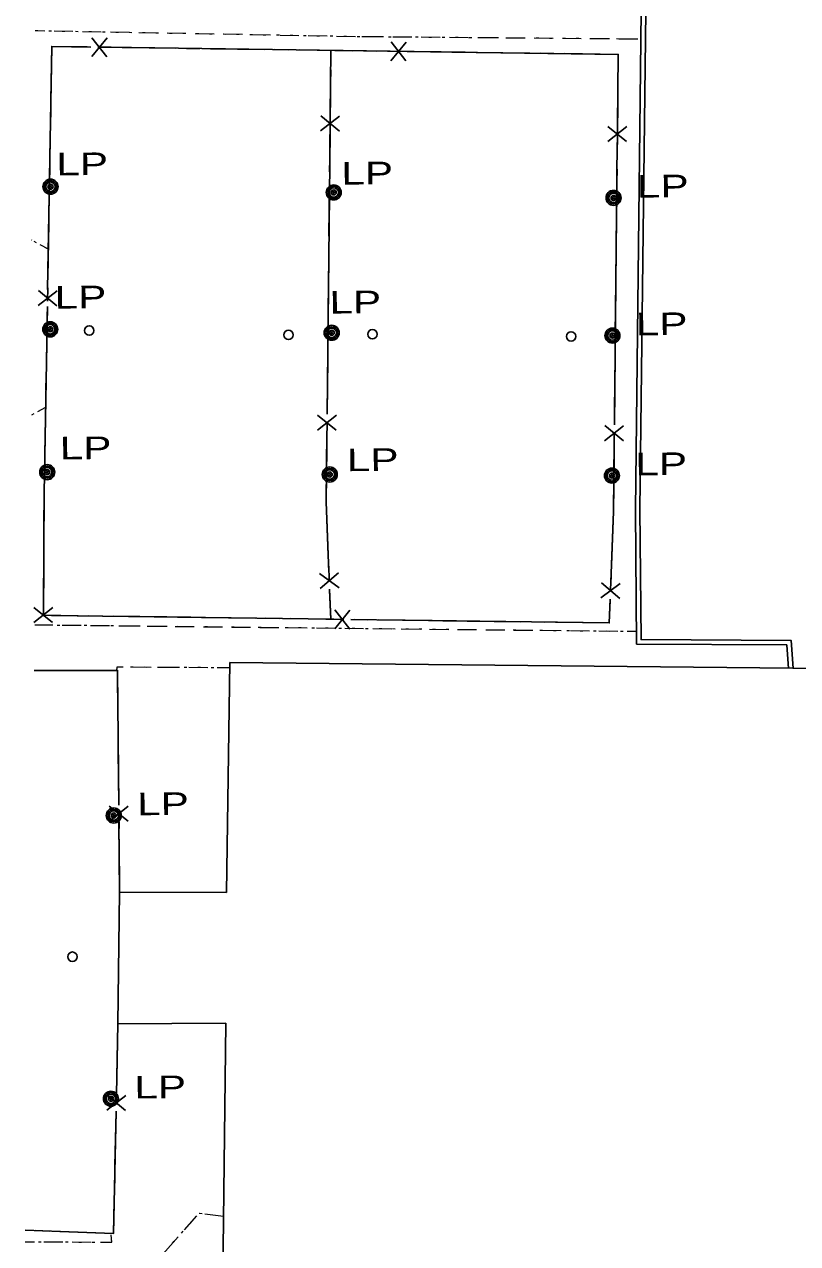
# Model space of a CAD drawing. Extents: x 2362213 to 2366494, y 6968794 to 6978110.
# Drawn here: x 2363840.6 to 2364004.9, y 6973596.3 to 6973855.4 of the extents above; entities that cross this region are included whole.
import ezdxf

# ---------------------------------------------------------------- set-up
doc = ezdxf.new("R2010")
doc.units = 0
doc.header["$LTSCALE"] = 1.9
doc.linetypes.add('DOTTED', pattern=[1.5, 0.3, -1.2])
doc.linetypes.add('LONG_DASH_SHORT_DASH', pattern=[9.9, 6, -1.2, 1.5, -1.2])
for name, color, linetype, lineweight in [('11', 7, 'Continuous', 25), ('13', 7, 'Continuous', 13), ('17', 7, 'Continuous', 25), ('2', 7, 'Continuous', 25), ('20', 7, 'Continuous', 25)]:
    doc.layers.add(name, color=color, linetype=linetype, lineweight=lineweight)

msp = doc.modelspace()

# ---------------------------------------------------------------- linework, layer by layer
at = {"layer": '11'}
msp.add_lwpolyline([(2363882.575, 6973571.486), (2363883.372, 6973643.127), (2363860.452, 6973643.018), (2363860.826, 6973671.023), (2363883.517, 6973670.959), (2363884.282, 6973719.809), (2364017.991, 6973718.463), (2364017.316, 6973661.333), (2364030.594, 6973657.349), (2364031.804, 6973749.765)], dxfattribs=at)
at = {"layer": '13'}
for p, q in [((2363842.911, 6973854.112), (2363844.912, 6973854.071)), ((2363846.912, 6973854.04), (2363850.913, 6973853.968)), ((2363852.914, 6973853.927), (2363856.915, 6973853.855)), ((2363858.915, 6973853.824), (2363862.916, 6973853.752)), ((2363864.916, 6973853.712), (2363868.917, 6973853.64)), ((2363870.918, 6973853.609), (2363874.918, 6973853.537)), ((2363876.918, 6973853.496), (2363880.92, 6973853.424)), ((2363882.92, 6973853.393), (2363886.921, 6973853.321)), ((2363888.921, 6973853.28), (2363892.922, 6973853.208)), ((2363894.923, 6973853.177), (2363898.924, 6973853.105)), ((2363900.924, 6973853.064), (2363904.925, 6973852.992)), ((2363906.925, 6973852.961), (2363910.926, 6973852.89)), ((2363912.927, 6973852.859), (2363916.927, 6973852.827)), ((2363918.927, 6973852.806), (2363922.929, 6973852.774)), ((2363924.928, 6973852.753), (2363928.929, 6973852.721)), ((2363930.929, 6973852.7), (2363934.929, 6973852.668)), ((2363936.93, 6973852.647), (2363940.93, 6973852.615)), ((2363942.93, 6973852.594), (2363946.931, 6973852.562)), ((2363948.931, 6973852.541), (2363952.932, 6973852.51)), ((2363954.932, 6973852.489), (2363958.933, 6973852.457)), ((2363960.933, 6973852.446), (2363964.933, 6973852.414)), ((2363966.934, 6973852.393), (2363970.934, 6973852.361)), ((2363842.195, 6973809.583), (2363842.135, 6973809.613)), ((2363845.684, 6973807.626), (2363843.935, 6973808.6)), ((2363845.114, 6973773.998), (2363843.353, 6973773.062)), ((2363846.655, 6973727.721), (2363842.785, 6973727.764)), ((2363852.656, 6973727.648), (2363848.655, 6973727.7)), ((2363858.657, 6973727.575), (2363854.655, 6973727.627)), ((2363864.658, 6973727.502), (2363860.657, 6973727.554)), ((2363870.659, 6973727.439), (2363866.658, 6973727.481)), ((2363876.66, 6973727.367), (2363872.659, 6973727.419)), ((2363882.661, 6973727.294), (2363878.66, 6973727.346)), ((2363888.662, 6973727.231), (2363884.661, 6973727.273)), ((2363894.663, 6973727.168), (2363890.662, 6973727.21)), ((2363900.664, 6973727.105), (2363896.663, 6973727.147)), ((2363906.664, 6973727.042), (2363902.664, 6973727.084)), ((2363912.665, 6973726.979), (2363908.665, 6973727.021)), ((2363918.666, 6973726.917), (2363914.666, 6973726.958)), ((2363924.667, 6973726.854), (2363920.666, 6973726.896)), ((2363930.668, 6973726.791), (2363926.667, 6973726.833)), ((2363936.669, 6973726.728), (2363932.668, 6973726.77)), ((2363942.67, 6973726.665), (2363938.669, 6973726.707)), ((2363948.67, 6973726.602), (2363944.671, 6973726.644)), ((2363954.671, 6973726.539), (2363950.671, 6973726.581)), ((2363960.672, 6973726.477), (2363956.672, 6973726.518)), ((2363966.674, 6973726.414), (2363962.672, 6973726.456)), ((2363970.674, 6973726.372), (2363968.674, 6973726.393)), ((2363863.55, 6973718.871), (2363867.551, 6973718.849)), ((2363869.551, 6973718.839), (2363873.551, 6973718.817)), ((2363875.551, 6973718.806), (2363879.552, 6973718.784)), ((2363881.552, 6973718.773), (2363884.262, 6973718.759)), ((2363878.968, 6973602.652), (2363882.912, 6973602.16)), ((2363874.59, 6973599.211), (2363877.252, 6973602.197)), ((2363870.593, 6973594.733), (2363873.254, 6973597.718)), ((2363840.752, 6973596.719), (2363842.753, 6973596.708)), ((2363844.753, 6973596.697), (2363848.753, 6973596.665)), ((2363850.753, 6973596.654), (2363854.754, 6973596.622))]:
    msp.add_line(p, q, dxfattribs=at)
at = {"layer": '13', "linetype": 'DOTTED'}
for p, q in [((2363845.684, 6973807.626), (2363842.135, 6973809.613)), ((2363845.114, 6973773.998), (2363841.652, 6973772.155)), ((2363970.674, 6973726.372), (2363842.785, 6973727.764))]:
    msp.add_line(p, q, dxfattribs=at)
for points in [[(2363842.911, 6973854.112), (2363912.277, 6973852.862), (2363971.624, 6973852.358)], [(2363860.217, 6973718.131), (2363860.32, 6973718.891), (2363884.262, 6973718.759)], [(2363840.592, 6973586.257), (2363862.588, 6973585.766), (2363877.787, 6973602.801), (2363882.912, 6973602.16)], [(2363840.752, 6973596.719), (2363859.174, 6973596.594), (2363859.026, 6973598.493)]]:
    msp.add_lwpolyline(points, dxfattribs=at)
at = {"layer": '13'}
for points in [[(2363860.217, 6973718.131), (2363860.32, 6973718.891), (2363861.55, 6973718.882)], [(2363856.754, 6973596.611), (2363859.174, 6973596.594), (2363859.049, 6973598.173)]]:
    msp.add_lwpolyline(points, dxfattribs=at)
at = {"layer": '17'}
for p, q in [((2363858.157, 6973852.547), (2363854.894, 6973848.585)), ((2363854.956, 6973852.587), (2363858.095, 6973848.545)), ((2363921.748, 6973851.663), (2363918.486, 6973847.7)), ((2363918.548, 6973851.702), (2363921.686, 6973847.661)), ((2363918.317, 6973849.73), (2363858.326, 6973850.569)), ((2363905.585, 6973836.187), (2363905.734, 6973849.91)), ((2363907.557, 6973835.956), (2363903.527, 6973832.798)), ((2363907.528, 6973832.766), (2363903.557, 6973835.998)), ((2363968.602, 6973833.708), (2363964.561, 6973830.549)), ((2363968.563, 6973830.517), (2363964.601, 6973833.75)), ((2363904.931, 6973772.588), (2363905.549, 6973832.587)), ((2363965.975, 6973770.339), (2363966.594, 6973830.339)), ((2363843.508, 6973795.684), (2363847.568, 6973798.823)), ((2363843.567, 6973798.885), (2363847.509, 6973795.622)), ((2363845.47, 6973795.453), (2363844.807, 6973755.905)), ((2363906.903, 6973772.367), (2363902.863, 6973769.208)), ((2363906.863, 6973769.166), (2363902.902, 6973772.409)), ((2363904.738, 6973753.985), (2363904.895, 6973768.987)), ((2363967.938, 6973770.118), (2363963.907, 6973766.959)), ((2363967.908, 6973766.917), (2363963.946, 6973770.16)), ((2363965.782, 6973751.736), (2363965.939, 6973766.739)), ((2363844.637, 6973731.712), (2363844.807, 6973755.905)), ((2363904.738, 6973753.985), (2363905.31, 6973739.001)), ((2363965.781, 6973751.876), (2363965.203, 6973736.89)), ((2363903.343, 6973738.722), (2363907.462, 6973735.68)), ((2363903.463, 6973735.522), (2363907.342, 6973738.87)), ((2363905.445, 6973735.401), (2363905.685, 6973729.023)), ((2363963.105, 6973733.56), (2363967.227, 6973736.609)), ((2363963.234, 6973736.761), (2363967.107, 6973733.408)), ((2363846.609, 6973731.501), (2363842.579, 6973728.322)), ((2363846.58, 6973728.3), (2363842.609, 6973731.523)), ((2363906.356, 6973729.009), (2363846.365, 6973729.828)), ((2363909.787, 6973730.932), (2363906.535, 6973726.981)), ((2363906.587, 6973730.982), (2363909.726, 6973726.931)), ((2363862.662, 6973686.101), (2363858.632, 6973689.263)), ((2363862.632, 6973689.301), (2363858.662, 6973686.063)), ((2363860.827, 6973670.883), (2363860.694, 6973685.883)), ((2363860.452, 6973643.018), (2363860.145, 6973628.025)), ((2363858.107, 6973624.665), (2363862.178, 6973627.784)), ((2363858.177, 6973627.866), (2363862.108, 6973624.583))]:
    msp.add_line(p, q, dxfattribs=at)
at = {"layer": '17', "linetype": 'LONG_DASH_SHORT_DASH'}
for q in [(2363905.734, 6973849.91), (2363905.685, 6973729.023)]:
    msp.add_line((2363904.738, 6973753.985), q, dxfattribs=at)
for points in [[(2363965.782, 6973751.736), (2363966.786, 6973849.061), (2363846.414, 6973850.735), (2363844.807, 6973755.905)], [(2363965.781, 6973751.876), (2363964.876, 6973728.217), (2363844.625, 6973729.852), (2363844.807, 6973755.905)], [(2363860.827, 6973670.883), (2363860.397, 6973718.132), (2363842.636, 6973718.113)], [(2363860.452, 6973643.018), (2363859.546, 6973598.478), (2363840.789, 6973599.149)]]:
    msp.add_lwpolyline(points, dxfattribs=at)
at = {"layer": '17'}
for points in [[(2363854.724, 6973850.614), (2363846.414, 6973850.735), (2363845.536, 6973799.053)], [(2363966.63, 6973833.939), (2363966.786, 6973849.061), (2363921.918, 6973849.684)], [(2363965.068, 6973733.289), (2363964.876, 6973728.217), (2363909.956, 6973728.964)], [(2363860.66, 6973689.483), (2363860.397, 6973718.132), (2363842.636, 6973718.113)], [(2363860.069, 6973624.424), (2363859.546, 6973598.478), (2363840.789, 6973599.149)]]:
    msp.add_lwpolyline(points, dxfattribs=at)
for centre in [(2363854.379, 6973790.368), (2363896.72, 6973789.431), (2363914.569, 6973789.571), (2363956.786, 6973789.123)]:
    msp.add_circle(centre, 1, dxfattribs=at)
at = {"layer": '2'}
msp.add_line((2363971.417, 6973752.3), (2363972.658, 6973858.258), dxfattribs=at)
for points in [[(2363970.457, 6973752.311), (2363971.698, 6973858.269), (2363972.658, 6973858.258)], [(2364002.98, 6973718.54), (2364002.622, 6973723.566), (2363970.699, 6973723.712), (2363970.457, 6973752.291)], [(2364003.939, 6973718.609), (2364003.513, 6973724.524), (2363971.65, 6973724.671), (2363971.417, 6973752.3)]]:
    msp.add_lwpolyline(points, dxfattribs=at)
at = {"layer": '20'}
for centre, radius in [((2363846.137, 6973820.941), 1.6), ((2363846.137, 6973820.941), 1.3), ((2363846.137, 6973820.941), 1), ((2363846.137, 6973820.941), 0.539), ((2363846.137, 6973820.941), 0.192), ((2363906.332, 6973819.724), 1.6), ((2363906.332, 6973819.724), 1.3), ((2363906.332, 6973819.724), 1), ((2363906.332, 6973819.724), 0.539), ((2363906.332, 6973819.724), 0.192), ((2363965.796, 6973818.56), 1.6), ((2363965.796, 6973818.56), 1.3), ((2363965.796, 6973818.56), 1), ((2363965.796, 6973818.56), 0.539), ((2363965.796, 6973818.56), 0.192), ((2363846.096, 6973790.629), 1.6), ((2363846.096, 6973790.629), 1.3), ((2363846.096, 6973790.629), 1), ((2363846.096, 6973790.629), 0.539), ((2363846.096, 6973790.629), 0.192), ((2363905.896, 6973789.888), 1.6), ((2363905.896, 6973789.888), 1.3), ((2363905.896, 6973789.888), 1), ((2363905.896, 6973789.888), 0.539), ((2363905.896, 6973789.888), 0.192), ((2363965.554, 6973789.286), 1.6), ((2363965.554, 6973789.286), 1.3), ((2363965.554, 6973789.286), 1), ((2363965.554, 6973789.286), 0.539), ((2363965.554, 6973789.286), 0.192), ((2363845.455, 6973760.271), 1.6), ((2363845.455, 6973760.271), 1.3), ((2363845.455, 6973760.271), 1), ((2363845.455, 6973760.271), 0.539), ((2363905.493, 6973759.773), 1.6), ((2363905.493, 6973759.773), 1.3), ((2363905.493, 6973759.773), 1), ((2363965.458, 6973759.534), 1.6), ((2363965.458, 6973759.534), 1.3), ((2363845.455, 6973760.271), 0.192), ((2363905.493, 6973759.773), 0.539), ((2363905.493, 6973759.773), 0.192), ((2363965.458, 6973759.534), 1), ((2363965.458, 6973759.534), 0.539), ((2363965.458, 6973759.534), 0.192), ((2363859.581, 6973687.292), 1.6), ((2363859.581, 6973687.292), 1.3), ((2363859.581, 6973687.292), 1), ((2363859.581, 6973687.292), 0.539), ((2363859.581, 6973687.292), 0.192), ((2363850.796, 6973657.287), 1), ((2363858.984, 6973627.104), 1.6), ((2363858.984, 6973627.104), 1.3), ((2363858.984, 6973627.104), 1), ((2363858.984, 6973627.104), 0.539), ((2363858.984, 6973627.104), 0.192)]:
    msp.add_circle(centre, radius, dxfattribs=at)

# ---------------------------------------------------------------- texts
at = {"layer": '20', "width": 1.4}
for p in [(2363842.405, 6973823.285), (2363902.976, 6973821.321), (2363965.796, 6973818.56), (2363842.045, 6973794.97), (2363900.447, 6973793.916), (2363965.554, 6973789.286), (2363843.13, 6973762.92), (2363904.146, 6973760.421), (2363965.458, 6973759.534), (2363859.581, 6973687.292), (2363858.984, 6973627.103)]:
    msp.add_text('  LP', height=4.8, rotation=0.546, dxfattribs=at).set_placement(p)

doc.saveas('drawing.dxf')
